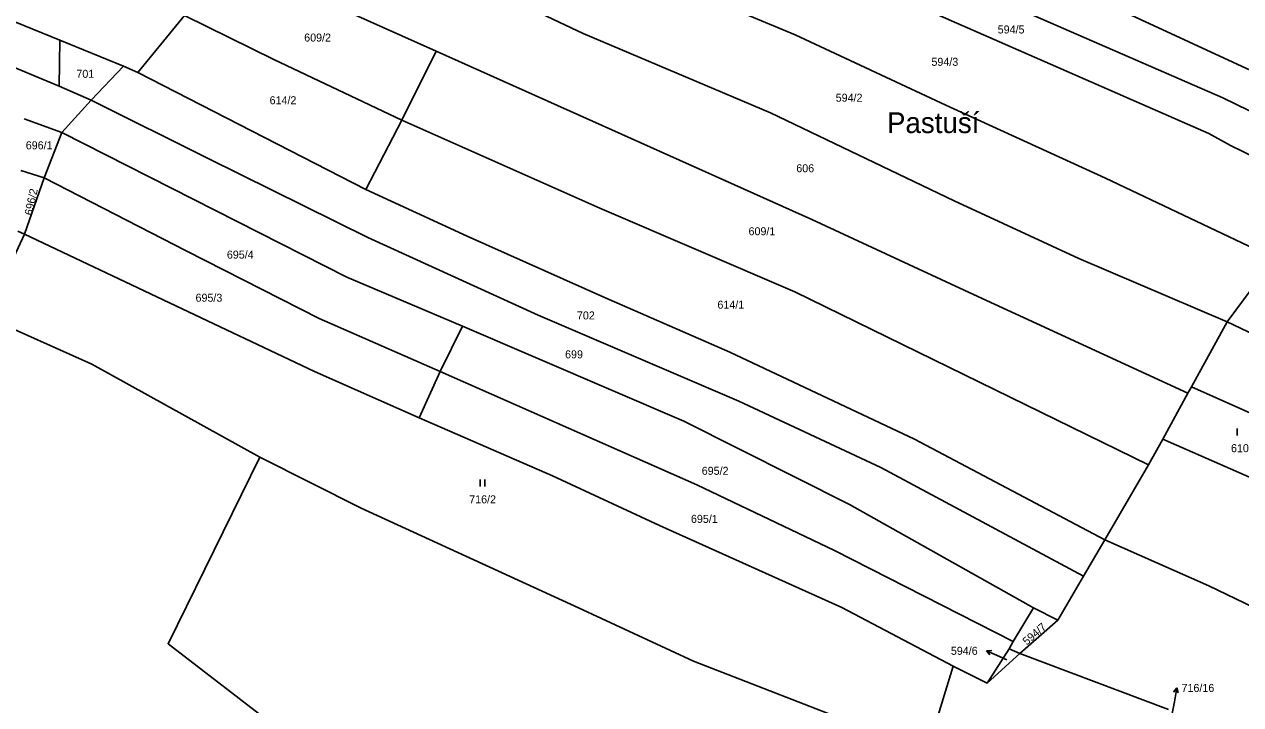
# Model space of a CAD drawing. Extents: x -751333 to -746055, y -1133395 to -1129777.
# Drawn here: x -748699.3 to -748441, y -1131157.3 to -1131012.8 of the extents above; entities that cross this region are included whole.
import ezdxf

# ---------------------------------------------------------------- set-up
doc = ezdxf.new("R2010")
doc.units = 0
for name, color, linetype in [('Hranice parcel', 7, 'Continuous'), ('Parcelní čísla', 7, 'Continuous'), ('Pop  PČ popisy', 7, 'Continuous'), ('Značky kultur', 7, 'Continuous')]:
    doc.layers.add(name, color=color, linetype=linetype)

msp = doc.modelspace()

# ---------------------------------------------------------------- linework, layer by layer
at = {"layer": 'Hranice parcel'}
for p, q in [((-748718.11, -1131005.41), (-748691.78, -1131016.23)), ((-748638.28, -1131006.71), (-748611.82, -1131018.52)), ((-748665.29, -1131010.97), (-748675.21, -1131023.11)), ((-748691.89, -1131026.01), (-748721.27, -1131013.77)), ((-748691.89, -1131026.01), (-748691.78, -1131016.23)), ((-748691.78, -1131016.23), (-748678.26, -1131021.72)), ((-748611.82, -1131018.52), (-748619.14, -1131033.17)), ((-748685.08, -1131028.93), (-748678.26, -1131021.72)), ((-748678.26, -1131021.72), (-748675.21, -1131023.11)), ((-748675.21, -1131023.11), (-748626.79, -1131047.92)), ((-748685.08, -1131028.93), (-748691.89, -1131026.01)), ((-748691.34, -1131035.8), (-748685.08, -1131028.93)), ((-748691.34, -1131035.8), (-748699.34, -1131032.91)), ((-748619.14, -1131033.17), (-748626.79, -1131047.92)), ((-748691.34, -1131035.8), (-748695.07, -1131045.45)), ((-748700.01, -1131043.9), (-748695.07, -1131045.45)), ((-748695.07, -1131045.45), (-748699.23, -1131057.41)), ((-748699.23, -1131057.41), (-748700.66, -1131056.76)), ((-748443.88, -1131076.03), (-748433.86, -1131062.5)), ((-748443.88, -1131076.03), (-748451.45, -1131089.82)), ((-748443.88, -1131076.03), (-748428.96, -1131083.09)), ((-748606.26, -1131076.91), (-748610.96, -1131086.6)), ((-748610.96, -1131086.6), (-748615.45, -1131096.38)), ((-748457.53, -1131100.91), (-748452.21, -1131091.2)), ((-748452.21, -1131091.2), (-748451.45, -1131089.82)), ((-748451.45, -1131089.82), (-748430.39, -1131099.21)), ((-748460.58, -1131106.38), (-748457.53, -1131100.91)), ((-748457.53, -1131100.91), (-748424, -1131115.63)), ((-748460.58, -1131106.38), (-748469.85, -1131122.34)), ((-748474.34, -1131130), (-748469.85, -1131122.34)), ((-748479.83, -1131139.36), (-748474.34, -1131130)), ((-748484.95, -1131136.78), (-748489.31, -1131143.89)), ((-748479.83, -1131139.36), (-748484.95, -1131136.78)), ((-748487.89, -1131146.41), (-748479.83, -1131139.36)), ((-748490.16, -1131145.46), (-748494.83, -1131152.76)), ((-748489.31, -1131143.89), (-748490.16, -1131145.46)), ((-748487.89, -1131146.41), (-748490.16, -1131145.46)), ((-748494.83, -1131152.76), (-748487.89, -1131146.41)), ((-748456.31, -1131158.34), (-748487.89, -1131146.41)), ((-748507.63, -1131167.31), (-748502.01, -1131149.16)), ((-748502.01, -1131149.16), (-748494.83, -1131152.76))]:
    msp.add_line(p, q, dxfattribs=at)
for points in [[(-748401.59, -1131039.86), (-748482.79, -1131002.25), (-748525.81, -1130981.98), (-748560.43, -1130965.34), (-748569.8, -1130959.62)], [(-748408.58, -1131046.09), (-748444.76, -1131028.43), (-748487.86, -1131009.7), (-748519.33, -1130996.05), (-748562.72, -1130976.46), (-748581.99, -1130964.07)], [(-748417.45, -1131050.74), (-748429.46, -1131045.22), (-748443.17, -1131038.57), (-748447.76, -1131036), (-748521.8, -1131003.51), (-748563.34, -1130984.99), (-748581.03, -1130975.42), (-748590.75, -1130967.27)], [(-748433.86, -1131062.5), (-748469.72, -1131045.54), (-748503.59, -1131029.98), (-748535.57, -1131015.06), (-748590.35, -1130992.22), (-748617.7, -1130976.74)], [(-748637.1, -1130988.07), (-748580.62, -1131014.77), (-748540.84, -1131031.61), (-748501.83, -1131050.32), (-748475.33, -1131062.6), (-748443.88, -1131076.03)], [(-748665.29, -1131010.97), (-748646.27, -1131020.35), (-748619.14, -1131033.17)], [(-748611.82, -1131018.52), (-748576.55, -1131034.33), (-748532.02, -1131054.31), (-748497.74, -1131070.23), (-748452.21, -1131091.2)], [(-748474.34, -1131130), (-748517.39, -1131106.95), (-748547.53, -1131092.9), (-748590.2, -1131074.61), (-748626.34, -1131058.09), (-748660.21, -1131041.32), (-748685.08, -1131028.93)], [(-748619.14, -1131033.17), (-748577.08, -1131051.86), (-748535.69, -1131069.64), (-748460.58, -1131106.38)], [(-748606.26, -1131076.91), (-748630.79, -1131066.52), (-748691.34, -1131035.8)], [(-748610.96, -1131086.6), (-748636.68, -1131075.28), (-748664.94, -1131060.97), (-748695.07, -1131045.45)], [(-748626.79, -1131047.92), (-748605.21, -1131057.83), (-748576.19, -1131070.76), (-748549.44, -1131082.45), (-748510.22, -1131100.96), (-748469.85, -1131122.34)], [(-748699.23, -1131057.41), (-748707.43, -1131074.93), (-748684.92, -1131085.04), (-748649.3, -1131104.79)], [(-748615.45, -1131096.38), (-748637.66, -1131086.57), (-748699.23, -1131057.41)], [(-748484.95, -1131136.78), (-748524.02, -1131114.8), (-748559.26, -1131097.09), (-748606.26, -1131076.91)], [(-748489.31, -1131143.89), (-748527.26, -1131124.6), (-748556.46, -1131110.63), (-748610.96, -1131086.6)], [(-748502.01, -1131149.16), (-748525.66, -1131136.67), (-748564.41, -1131119.26), (-748587.13, -1131108.7), (-748615.45, -1131096.38)], [(-748441.17, -1131464.36), (-748441.27, -1131454.86), (-748468.06, -1131411.28), (-748480.68, -1131390.05), (-748513.08, -1131337.18), (-748535.65, -1131293.82), (-748524.03, -1131286.83), (-748537.13, -1131261.56), (-748549.98, -1131235.81), (-748668.77, -1131144.37), (-748649.3, -1131104.79)], [(-748649.3, -1131104.79), (-748627.72, -1131115.56), (-748581.58, -1131136.72), (-748557.17, -1131148.05), (-748507.63, -1131167.31)], [(-748469.85, -1131122.34), (-748447.76, -1131132.08), (-748432.29, -1131139.48), (-748408.02, -1131150.06), (-748389.42, -1131156.09)]]:
    msp.add_lwpolyline(points, dxfattribs=at)
at = {"layer": 'Pop  PČ popisy'}
for p, q in [((-748494.942, -1131145.889), (-748493.823, -1131145.839)), ((-748492.2, -1131147.11), (-748494.942, -1131145.889)), ((-748494.942, -1131145.889), (-748494.23, -1131146.754)), ((-748490.65, -1131147.82), (-748492.2, -1131147.11)), ((-748454.549, -1131153.755), (-748455.216, -1131154.654)), ((-748455.07, -1131156.71), (-748454.549, -1131153.755)), ((-748454.549, -1131153.755), (-748454.23, -1131154.828)), ((-748455.58, -1131159.57), (-748455.07, -1131156.71))]:
    msp.add_line(p, q, dxfattribs=at)
at = {"layer": 'Značky kultur'}
for p, q in [((-748441.721, -1131100.14), (-748441.721, -1131098.64)), ((-748602.471, -1131111.01), (-748602.471, -1131109.51)), ((-748601.47, -1131111.01), (-748601.47, -1131109.51))]:
    msp.add_line(p, q, dxfattribs=at)

# ---------------------------------------------------------------- texts
at = {"layer": 'Parcelní čísla'}
for s, p in [('594/5', (-748492.58, -1131014.79)), ('609/2', (-748639.85, -1131016.51)), ('594/3', (-748506.65, -1131021.66)), ('701', (-748688.23, -1131024.21)), ('594/2', (-748526.98, -1131029.28)), ('614/2', (-748647.2, -1131029.82)), ('696/1', (-748698.98, -1131039.39)), ('606', (-748535.35, -1131044.26)), ('609/1', (-748545.49, -1131057.64)), ('695/4', (-748656.27, -1131062.6)), ('695/3', (-748662.93, -1131071.75)), ('614/1', (-748552.1, -1131073.23)), ('702', (-748581.93, -1131075.51)), ('699', (-748584.45, -1131083.77)), ('610', (-748443.04, -1131103.7)), ('695/2', (-748555.43, -1131108.5)), ('716/2', (-748604.81, -1131114.56)), ('695/1', (-748557.72, -1131118.71)), ('594/6', (-748502.527, -1131146.72)), ('716/16', (-748453.54, -1131154.61))]:
    msp.add_text(s, height=1.7, dxfattribs=at).set_placement(p)
for s, rotation, p in [('696/2', 78, (-748697.608, -1131053.506)), ('594/7', 41, (-748486.382, -1131144.791))]:
    msp.add_text(s, height=1.7, rotation=rotation, dxfattribs=at).set_placement(p)
at = {"layer": 'Pop  PČ popisy'}
msp.add_text('Pastuší', height=4.4, dxfattribs=at).set_placement((-748516.093, -1131035.94))

doc.saveas('drawing.dxf')
